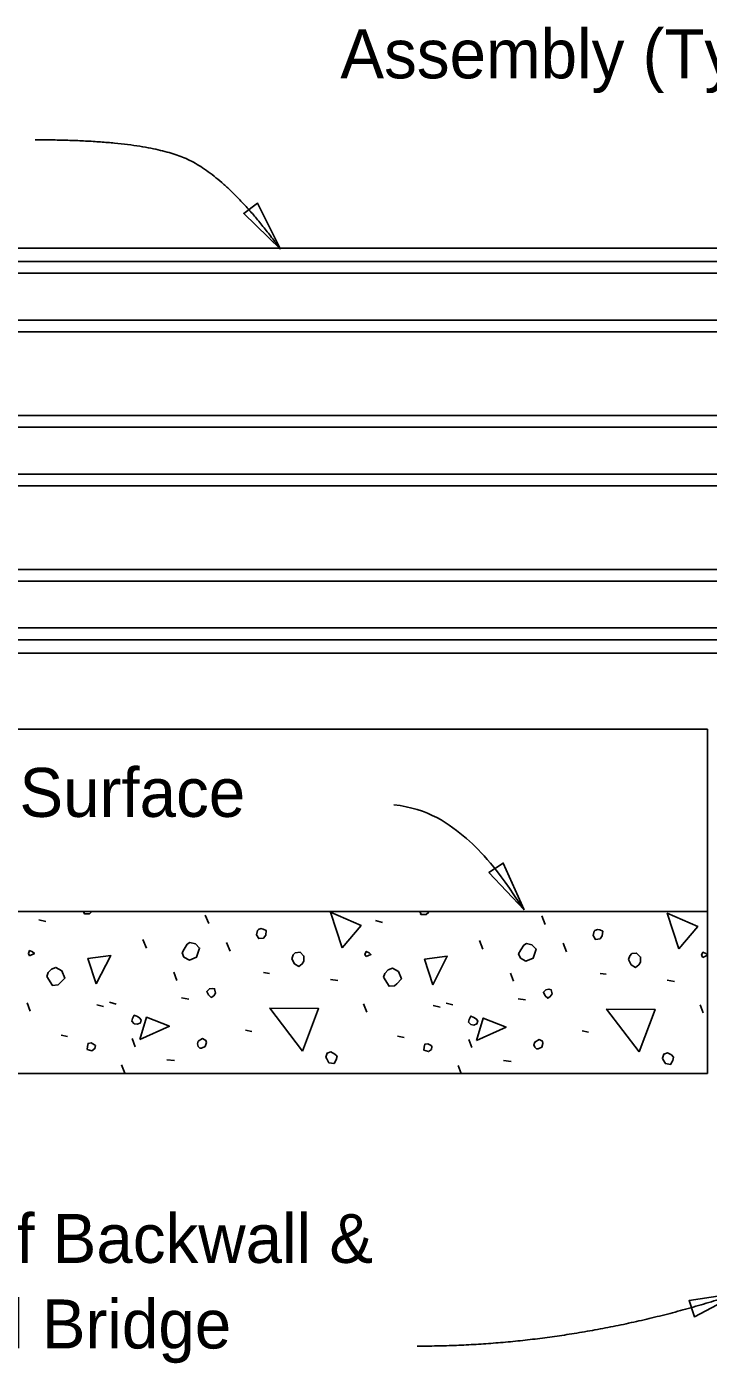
# Model space of a CAD drawing. Extents: x 21587 to 21656.3, y 56117.4 to 56157.3.
# Drawn here: x 21610.68 to 21613.49, y 56132.19 to 56137.69 of the extents above; entities that cross this region are included whole.
import ezdxf

# ---------------------------------------------------------------- set-up
doc = ezdxf.new("R2010")
doc.units = 0
for name, color, linetype in [('AdhocPoint_dp', 7, 'Continuous'), ('Border', 7, 'Continuous'), ('PlotBorder_dp', 7, 'Continuous'), ('SheetBorder_dp', 7, 'Continuous'), ('TextMisc', 7, 'Continuous')]:
    doc.layers.add(name, color=color, linetype=linetype)

msp = doc.modelspace()

# ---------------------------------------------------------------- linework, layer by layer
at = {"layer": 'AdhocPoint_dp'}
for p, q in [((21607.3117, 56134.8009), (21613.4854, 56134.8009)), ((21613.4854, 56134.8008), (21613.4854, 56133.3842)), ((21613.4854, 56134.0509), (21607.3117, 56134.0509)), ((21607.3117, 56133.3843), (21613.4854, 56133.3843))]:
    msp.add_line(p, q, dxfattribs=at)
at = {"layer": 'Border'}
for p, q in [((21619.5663, 56136.7801), (21607.3117, 56136.7801)), ((21607.3117, 56136.7246), (21619.5663, 56136.7246)), ((21607.3117, 56136.6764), (21619.5663, 56136.6764)), ((21607.3117, 56136.4835), (21619.5663, 56136.4835)), ((21607.3117, 56136.4353), (21619.5663, 56136.4353)), ((21607.3117, 56136.0914), (21619.5663, 56136.0914)), ((21607.3117, 56136.0431), (21619.5663, 56136.0431)), ((21607.3117, 56135.8503), (21619.5663, 56135.8503)), ((21607.3117, 56135.8022), (21619.5663, 56135.8022)), ((21607.3117, 56135.4582), (21619.5663, 56135.4582)), ((21607.3117, 56135.41), (21619.5663, 56135.41)), ((21607.3117, 56135.2172), (21619.5663, 56135.2172)), ((21607.3117, 56135.169), (21619.5663, 56135.169)), ((21619.5663, 56135.1134), (21607.3117, 56135.1134))]:
    msp.add_line(p, q, dxfattribs=at)
at = {"layer": 'PlotBorder_dp'}
for points in [[(21611.7282, 56136.7755), (21611.6337, 56136.9644), (21611.5768, 56136.9228)], [(21612.7308, 56134.0576), (21612.6444, 56134.2503), (21612.5857, 56134.211)], [(21613.6179, 56132.4823), (21613.4091, 56132.4504), (21613.4313, 56132.3834)]]:
    msp.add_lwpolyline(points, close=True, dxfattribs=at)
for points, degree in [([(21610.7197, 56137.2255), (21611.1414, 56137.2255), (21611.5012, 56137.086), (21611.7282, 56136.7756)], 2), ([(21612.194, 56134.4896), (21612.3358, 56134.4753), (21612.5127, 56134.3451), (21612.6101, 56134.2379), (21612.7308, 56134.0575)], 3), ([(21613.6179, 56132.4823), (21612.9542, 56132.2627), (21612.2905, 56132.2627)], 2)]:
    msp.add_open_spline(points, degree=degree, dxfattribs=at)
at = {"layer": 'TextMisc'}
for p, q in [((21610.7346, 56134.0167), (21610.7629, 56134.0096)), ((21611.4329, 56134.0008), (21611.4187, 56134.0362)), ((21612.1193, 56134.0132), (21612.1476, 56134.0061)), ((21612.8175, 56133.9973), (21612.8034, 56134.0326)), ((21611.1765, 56133.9), (21611.1624, 56133.9354)), ((21611.5206, 56133.8883), (21611.5065, 56133.9237)), ((21612.5612, 56133.8965), (21612.5471, 56133.9319)), ((21612.9053, 56133.8848), (21612.8912, 56133.9201)), ((21611.302, 56133.7675), (21611.2897, 56133.801)), ((21611.6585, 56133.7999), (21611.6833, 56133.7964)), ((21611.9343, 56133.7716), (21611.9643, 56133.7663)), ((21612.6867, 56133.7639), (21612.6743, 56133.7975)), ((21613.0432, 56133.7964), (21613.0679, 56133.7928)), ((21613.319, 56133.7681), (21613.349, 56133.7628)), ((21610.6981, 56133.6408), (21610.6857, 56133.6744)), ((21610.9721, 56133.6673), (21611.0004, 56133.6603)), ((21611.0245, 56133.6773), (21611.0528, 56133.6702)), ((21611.3209, 56133.6956), (21611.3509, 56133.6903)), ((21612.0828, 56133.6373), (21612.0704, 56133.6709)), ((21612.3568, 56133.6638), (21612.3851, 56133.6567)), ((21612.4092, 56133.6738), (21612.4375, 56133.6667)), ((21612.7055, 56133.6921), (21612.7356, 56133.6868)), ((21613.4674, 56133.6337), (21613.4551, 56133.6673)), ((21611.5843, 56133.563), (21611.6108, 56133.5577)), ((21612.9689, 56133.5595), (21612.9955, 56133.5542)), ((21610.8254, 56133.5418), (21610.8519, 56133.5365)), ((21611.1306, 56133.4947), (21611.1182, 56133.5283)), ((21612.21, 56133.5383), (21612.2366, 56133.533)), ((21612.5152, 56133.4912), (21612.5029, 56133.5248)), ((21611.2608, 56133.4411), (21611.2926, 56133.4375)), ((21611.0881, 56133.3851), (21611.074, 56133.4205)), ((21612.4717, 56133.3843), (21612.4587, 56133.4169)), ((21612.6454, 56133.4375), (21612.6773, 56133.434))]:
    msp.add_line(p, q, dxfattribs=at)
for points in [[(21610.9179, 56134.0509), (21610.922, 56134.0415), (21610.9184, 56134.045)], [(21610.922, 56134.0415), (21610.9432, 56134.0415), (21610.9527, 56134.0509)], [(21611.982, 56133.9007), (21611.9343, 56134.0474), (21612.0598, 56133.9926), (21611.982, 56133.9007)], [(21612.3017, 56134.0509), (21612.3013, 56134.0503), (21612.3067, 56134.0379), (21612.3031, 56134.0415)], [(21612.3067, 56134.0379), (21612.3279, 56134.0379), (21612.3385, 56134.0485), (21612.3378, 56134.0509)], [(21613.3667, 56133.8971), (21613.319, 56134.0439), (21613.4445, 56133.9891), (21613.3667, 56133.8971)], [(21611.6302, 56133.9555), (21611.6391, 56133.9396), (21611.6585, 56133.9413), (21611.6673, 56133.9537), (21611.6691, 56133.9731), (21611.6567, 56133.9785), (21611.6479, 56133.9802), (21611.6373, 56133.9767), (21611.6338, 56133.9731), (21611.6302, 56133.9555)], [(21613.0149, 56133.9519), (21613.0237, 56133.936), (21613.0432, 56133.9378), (21613.052, 56133.9502), (21613.0538, 56133.9696), (21613.0414, 56133.9749), (21613.0326, 56133.9767), (21613.022, 56133.9731), (21613.0184, 56133.9696), (21613.0149, 56133.9519)], [(21610.6963, 56133.8689), (21610.7158, 56133.8777), (21610.7087, 56133.8848), (21610.6963, 56133.8901), (21610.691, 56133.8777), (21610.6963, 56133.8689)], [(21611.3303, 56133.8629), (21611.3533, 56133.8505), (21611.3834, 56133.8629), (21611.3957, 56133.9), (21611.3781, 56133.9177), (21611.3551, 56133.923), (21611.3445, 56133.916), (21611.3321, 56133.8965), (21611.3233, 56133.8806), (21611.3303, 56133.8629)], [(21611.7752, 56133.8565), (21611.7858, 56133.8353), (21611.8035, 56133.8247), (21611.8176, 56133.8353), (21611.8247, 56133.8459), (21611.8247, 56133.8671), (21611.8088, 56133.883), (21611.7893, 56133.8812), (21611.7805, 56133.8724), (21611.7752, 56133.8565)], [(21612.081, 56133.8653), (21612.1004, 56133.8742), (21612.0934, 56133.8812), (21612.081, 56133.8865), (21612.0757, 56133.8742), (21612.081, 56133.8653)], [(21612.715, 56133.8594), (21612.738, 56133.847), (21612.768, 56133.8594), (21612.7804, 56133.8965), (21612.7627, 56133.9142), (21612.7398, 56133.9195), (21612.7291, 56133.9124), (21612.7168, 56133.893), (21612.7079, 56133.8771), (21612.715, 56133.8594)], [(21613.4657, 56133.8618), (21613.4851, 56133.8706), (21613.4781, 56133.8777), (21613.4657, 56133.883), (21613.4604, 56133.8706), (21613.4657, 56133.8618)], [(21610.9697, 56133.7533), (21610.9361, 56133.8576), (21611.0298, 56133.87), (21610.9697, 56133.7533)], [(21612.3544, 56133.7498), (21612.3208, 56133.8541), (21612.4145, 56133.8665), (21612.3544, 56133.7498)], [(21613.1599, 56133.8529), (21613.1705, 56133.8317), (21613.1881, 56133.8211), (21613.2023, 56133.8317), (21613.2094, 56133.8423), (21613.2094, 56133.8635), (21613.1934, 56133.8795), (21613.174, 56133.8777), (21613.1652, 56133.8689), (21613.1599, 56133.8529)], [(21610.767, 56133.784), (21610.79, 56133.7469), (21610.813, 56133.7486), (21610.8218, 56133.7575), (21610.8413, 56133.7769), (21610.8289, 56133.807), (21610.8042, 56133.8211), (21610.7865, 56133.814), (21610.7723, 56133.7999), (21610.767, 56133.784)], [(21612.1517, 56133.7805), (21612.1747, 56133.7433), (21612.1977, 56133.7451), (21612.2065, 56133.7539), (21612.226, 56133.7734), (21612.2136, 56133.8034), (21612.1888, 56133.8176), (21612.1712, 56133.8105), (21612.157, 56133.7964), (21612.1517, 56133.7805)], [(21611.4322, 56133.708), (21611.4428, 56133.6974), (21611.4534, 56133.7044), (21611.4605, 56133.7151), (21611.457, 56133.7327), (21611.4481, 56133.7345), (21611.4358, 56133.7327), (21611.4252, 56133.7221), (21611.4322, 56133.708)], [(21612.8169, 56133.7044), (21612.8275, 56133.6938), (21612.8381, 56133.7009), (21612.8452, 56133.7115), (21612.8417, 56133.7292), (21612.8328, 56133.731), (21612.8204, 56133.7292), (21612.8098, 56133.7186), (21612.8169, 56133.7044)], [(21611.127, 56133.5889), (21611.1394, 56133.5871), (21611.1518, 56133.5925), (21611.1553, 56133.6031), (21611.15, 56133.6119), (21611.1394, 56133.619), (21611.127, 56133.6243), (21611.12, 56133.6101), (21611.1164, 56133.5995), (21611.127, 56133.5889)], [(21611.1494, 56133.5241), (21611.1777, 56133.6161), (21611.2714, 56133.5789), (21611.1494, 56133.5241)], [(21611.8194, 56133.4764), (21611.685, 56133.6532), (21611.8848, 56133.6514), (21611.8194, 56133.4764)], [(21612.5117, 56133.5854), (21612.5241, 56133.5836), (21612.5365, 56133.5889), (21612.54, 56133.5995), (21612.5347, 56133.6084), (21612.5241, 56133.6154), (21612.5117, 56133.6207), (21612.5046, 56133.6066), (21612.5011, 56133.596), (21612.5117, 56133.5854)], [(21612.5341, 56133.5206), (21612.5624, 56133.6125), (21612.656, 56133.5754), (21612.5341, 56133.5206)], [(21613.2041, 56133.4729), (21613.0697, 56133.6496), (21613.2695, 56133.6479), (21613.2041, 56133.4729)], [(21610.9332, 56133.4835), (21610.9527, 56133.4782), (21610.965, 56133.487), (21610.9668, 56133.4994), (21610.9633, 56133.5029), (21610.9491, 56133.51), (21610.9367, 56133.5082), (21610.935, 56133.4959), (21610.9332, 56133.4835)], [(21611.3969, 56133.4888), (21611.4039, 56133.4888), (21611.4181, 56133.4959), (21611.4234, 56133.5118), (21611.4216, 56133.5206), (21611.4075, 56133.5277), (21611.3898, 56133.5171), (21611.3863, 56133.5065), (21611.3898, 56133.4959), (21611.3969, 56133.4888)], [(21612.3179, 56133.4799), (21612.3373, 56133.4746), (21612.3497, 56133.4835), (21612.3515, 56133.4959), (21612.3479, 56133.4994), (21612.3338, 56133.5065), (21612.3214, 56133.5047), (21612.3197, 56133.4923), (21612.3179, 56133.4799)], [(21612.7816, 56133.4852), (21612.7886, 56133.4852), (21612.8028, 56133.4923), (21612.8081, 56133.5082), (21612.8063, 56133.5171), (21612.7922, 56133.5241), (21612.7745, 56133.5135), (21612.7709, 56133.5029), (21612.7745, 56133.4923), (21612.7816, 56133.4852)], [(21611.9184, 56133.4446), (21611.9272, 56133.4287), (21611.9484, 56133.4251), (21611.9573, 56133.4411), (21611.9608, 56133.4552), (21611.952, 56133.464), (21611.936, 56133.4729), (21611.9201, 56133.4676), (21611.9148, 56133.4517), (21611.9184, 56133.4446)], [(21613.303, 56133.4411), (21613.3119, 56133.4251), (21613.3331, 56133.4216), (21613.3419, 56133.4375), (21613.3455, 56133.4517), (21613.3366, 56133.4605), (21613.3207, 56133.4693), (21613.3048, 56133.464), (21613.2995, 56133.4481), (21613.303, 56133.4411)]]:
    msp.add_lwpolyline(points, dxfattribs=at)

# ---------------------------------------------------------------- texts
at = {"layer": 'PlotBorder_dp'}
for s, p in [('Assembly (Typ.)', (21611.9745, 56137.4784)), ('Front Face of Backwall &', (21609.1128, 56132.6051)), ('Begin or End Bridge', (21609.1128, 56132.2531))]:
    msp.add_text(s, height=0.2016, dxfattribs=at).set_placement(p)
at = {"layer": 'SheetBorder_dp'}
msp.add_text('Final Riding Surface', height=0.2016, dxfattribs=at).set_placement((21609.1559, 56134.44))

doc.saveas('drawing.dxf')
